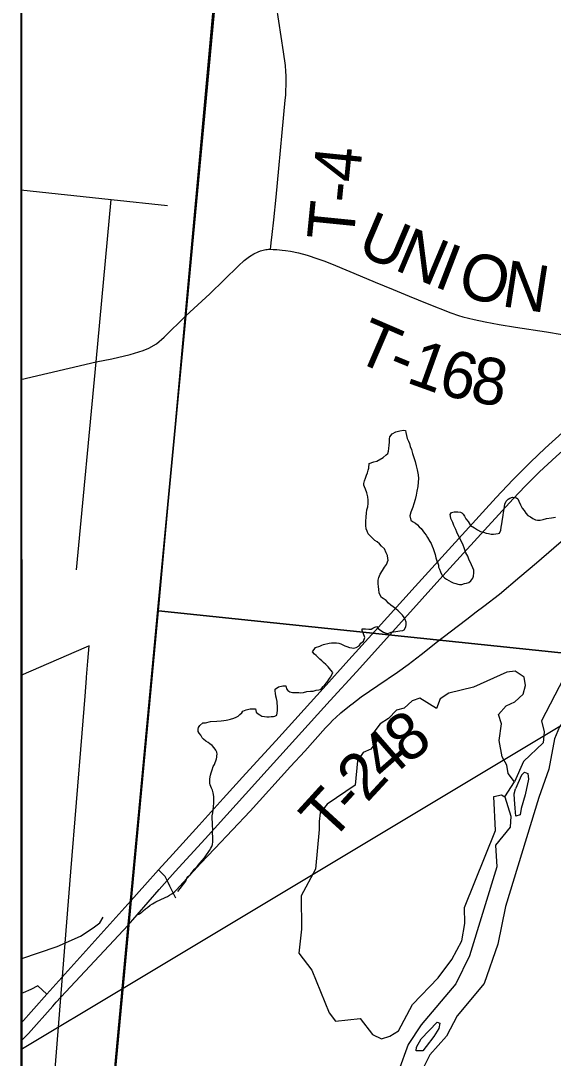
# Model space of a CAD drawing. Extents: x -1.4 to 35.4, y 0 to 22.
# Drawn here: x 24.49 to 25.138, y 16.414 to 17.676 of the extents above; entities that cross this region are included whole.
import ezdxf

# ---------------------------------------------------------------- set-up
doc = ezdxf.new("R2010")
doc.units = 0
for name, color, linetype in [('GM_X_City_Street', 7, 'Continuous'), ('GM_X_County_Text', 7, 'Continuous'), ('GM_X_Interchange_Ramps', 7, 'Continuous'), ('GM_X_Major_River', 7, 'Continuous'), ('GM_X_Minor_Lake', 7, 'Continuous'), ('GM_X_Minor_River', 7, 'Continuous'), ('GM_X_Rail_Line', 7, 'Continuous'), ('GM_X_Section', 7, 'Continuous'), ('GM_X_State_Route', 7, 'Continuous'), ('GM_X_Township_Road', 7, 'Continuous'), ('GM_X_Township_Road_Text', 7, 'Continuous'), ('SC_Scratch1', 7, 'Continuous'), ('SH_Border', 7, 'Continuous'), ('SH_Cut_Line', 7, 'Continuous')]:
    doc.layers.add(name, color=color, linetype=linetype)

msp = doc.modelspace()

# ---------------------------------------------------------------- linework, layer by layer
at = {"layer": 'GM_X_City_Street'}
for points in [[(24.4897, 17.47), (24.5998, 17.4582), (24.6682, 17.451)], [(24.5575, 17.008), (24.5813, 17.2609), (24.5998, 17.4582)], [(24.4897, 17.2395), (24.5813, 17.2609), (24.6004, 17.2644), (24.6228, 17.2697), (24.6386, 17.2746), (24.6457, 17.2776), (24.6551, 17.2829), (24.6642, 17.2908), (24.6908, 17.3168)], [(24.4897, 16.5348), (24.534, 16.5499), (24.5624, 16.5623), (24.578, 16.5727), (24.5858, 16.5787), (24.5899, 16.5854)]]:
    msp.add_lwpolyline(points, dxfattribs=at)
at = {"layer": 'GM_X_County_Text'}
msp.add_lwpolyline([(24.4897, 16.8794), (24.4897, 15.8886), (24.4962, 15.9571), (24.5508, 16.6406), (24.5643, 16.8095), (24.5679, 16.8544), (24.5697, 16.8763), (24.5697, 16.8774), (24.5713, 16.8967), (24.5728, 16.9155), (24.5693, 16.9139)], close=True, dxfattribs=at)
at = {"layer": 'GM_X_Interchange_Ramps'}
msp.add_lwpolyline([(24.5216, 16.4921), (24.5104, 16.5021), (24.5019, 16.4976), (24.4925, 16.4935), (24.4897, 16.4927)], dxfattribs=at)
at = {"layer": 'GM_X_Major_River'}
for points in [[(25.2185, 16.9085), (25.1999, 16.8899), (25.1453, 16.817), (25.1393, 16.8023), (25.1326, 16.7657), (25.1204, 16.7311), (25.0798, 16.5986), (25.0703, 16.5526), (25.0539, 16.5048), (25.021, 16.4655), (25.0079, 16.4408), (24.9876, 16.4182), (24.9772, 16.3972)], [(25.1502, 16.8757), (25.1235, 16.8244), (25.1266, 16.811), (25.1255, 16.7974), (25.1018, 16.7749), (25.0908, 16.7502)], [(25.0993, 16.7584), (25.1028, 16.7617), (25.1069, 16.7601), (25.1079, 16.7533), (25.1037, 16.7343), (25.0989, 16.7177), (25.0976, 16.7101), (25.0922, 16.7084), (25.0917, 16.7183), (25.0907, 16.7285), (25.0901, 16.7354), (25.0921, 16.7418)], [(25.0993, 16.7584), (25.0921, 16.7418)], [(25.079, 16.7319), (25.0908, 16.7502)], [(25.079, 16.7319), (25.0864, 16.7085), (25.0853, 16.6949), (25.0677, 16.6733), (25.0693, 16.6467), (25.0358, 16.5387), (25.0194, 16.5046), (24.9771, 16.4545), (24.9613, 16.4307), (24.9495, 16.3983)], [(24.9965, 16.458), (24.9999, 16.4568), (24.9986, 16.45), (24.9924, 16.4406), (24.983, 16.4283), (24.9791, 16.423), (24.9708, 16.4232), (24.9716, 16.4274), (24.9771, 16.4375)], [(24.9965, 16.458), (24.9771, 16.4375)]]:
    msp.add_lwpolyline(points, dxfattribs=at)
at = {"layer": 'GM_X_Minor_Lake'}
for points in [[(25.0908, 16.7502), (25.083, 16.7602), (25.0813, 16.7705), (25.0755, 16.7805), (25.0721, 16.8003), (25.0748, 16.8208), (25.0712, 16.8319), (25.0805, 16.8424), (25.0912, 16.8475), (25.1013, 16.8568), (25.1041, 16.8673), (25.1025, 16.8776), (25.0916, 16.8847), (25.0813, 16.8834), (25.0408, 16.8652), (25.0106, 16.8578), (25.0003, 16.8512), (24.9958, 16.8395), (24.9756, 16.8517), (24.9661, 16.8485), (24.9564, 16.8396), (24.9469, 16.8371), (24.9372, 16.827), (24.9272, 16.8208), (24.9194, 16.8107), (24.9233, 16.7996), (24.9159, 16.7898), (24.9064, 16.7858), (24.8997, 16.7757), (24.8969, 16.7461), (24.8626, 16.7229), (24.8541, 16.7124), (24.8531, 16.7018), (24.8529, 16.6923), (24.8485, 16.6441), (24.8312, 16.6114), (24.8315, 16.5711), (24.8282, 16.5416), (24.8441, 16.5211), (24.8651, 16.4694), (24.8729, 16.459), (24.9029, 16.4622), (24.9177, 16.4429), (24.929, 16.4377), (24.9389, 16.4409), (24.9493, 16.4472), (24.9666, 16.4795), (24.9976, 16.5116), (25.0144, 16.534), (25.0266, 16.5566), (25.0304, 16.5778), (25.0297, 16.5972), (25.0676, 16.691), (25.0654, 16.7325), (25.0749, 16.7345), (25.079, 16.7319), (25.079, 16.7319)], [(25.079, 16.7319), (25.0908, 16.7502)]]:
    msp.add_lwpolyline(points, dxfattribs=at)
at = {"layer": 'GM_X_Minor_River'}
for points in [[(24.9247, 16.9909), (24.9247, 16.9931), (24.9248, 16.9954), (24.9256, 16.9988), (24.9272, 17.0026), (24.9299, 17.0071), (24.9326, 17.0113), (24.935, 17.0143), (24.9369, 17.0196), (24.9366, 17.0218), (24.9359, 17.0253), (24.9344, 17.0287), (24.9326, 17.0333), (24.9289, 17.0368), (24.9262, 17.0395), (24.9236, 17.0418), (24.9206, 17.0438), (24.918, 17.0465), (24.915, 17.0492), (24.9124, 17.0519), (24.9113, 17.055), (24.9102, 17.058), (24.9099, 17.0618), (24.9096, 17.0668), (24.9101, 17.0725), (24.9105, 17.077), (24.911, 17.0808), (24.9122, 17.0846), (24.9126, 17.0888), (24.9127, 17.0926), (24.912, 17.0968), (24.9109, 17.1014), (24.9095, 17.106), (24.908, 17.109), (24.9073, 17.1109), (24.9073, 17.1128), (24.9081, 17.1162), (24.9093, 17.1196), (24.9105, 17.123), (24.9117, 17.1261), (24.9125, 17.1291), (24.9133, 17.1317), (24.9133, 17.1336), (24.9137, 17.1355), (24.9138, 17.1374), (24.9195, 17.1393), (24.9233, 17.14), (24.931, 17.1444), (24.9344, 17.1478), (24.9364, 17.1496), (24.9372, 17.1523), (24.9376, 17.1557), (24.938, 17.1595), (24.9385, 17.1633), (24.9385, 17.1671), (24.939, 17.1697), (24.9417, 17.1735), (24.9463, 17.1757), (24.9512, 17.1771), (24.9554, 17.1778), (24.9581, 17.1774), (24.9584, 17.1751), (24.9591, 17.1713), (24.9602, 17.1675), (24.9617, 17.1644), (24.9627, 17.1614), (24.9638, 17.1579), (24.9653, 17.1541), (24.9667, 17.1495), (24.9682, 17.1445), (24.9696, 17.1396), (24.971, 17.1346), (24.9721, 17.1296), (24.9735, 17.1235), (24.9738, 17.119), (24.9734, 17.1144), (24.9729, 17.1091), (24.9717, 17.1038), (24.9709, 17.0989), (24.9696, 17.0936), (24.968, 17.0883), (24.9668, 17.0841), (24.9652, 17.0803), (24.9644, 17.0781), (24.9632, 17.0735), (24.9647, 17.0682), (24.9665, 17.0666), (24.9703, 17.0647), (24.9726, 17.0627), (24.9748, 17.0604), (24.977, 17.0581), (24.9811, 17.0527), (24.983, 17.05), (24.9848, 17.0473), (24.9878, 17.0423), (24.9893, 17.04), (24.9904, 17.0369), (24.9918, 17.0339), (24.9929, 17.0304), (24.994, 17.0266), (24.9951, 17.0224)], [(24.9951, 17.0224), (24.9962, 17.019), (24.9972, 17.0159), (24.998, 17.0136), (24.9983, 17.0113), (24.9994, 17.0087), (25.0005, 17.0056), (25.0023, 17.0018), (25.0053, 16.9983), (25.0079, 16.9964), (25.0106, 16.9948), (25.0136, 16.9932), (25.0162, 16.992), (25.0192, 16.9912), (25.0219, 16.9904), (25.0238, 16.99), (25.0264, 16.9903), (25.0299, 16.9914), (25.0322, 16.9918), (25.0352, 16.9925), (25.0375, 16.9944), (25.0398, 16.9977), (25.0407, 17.0004), (25.0411, 17.0042), (25.0411, 17.0076), (25.0371, 17.0168), (25.0356, 17.0199), (25.0338, 17.0245), (25.0316, 17.0287), (25.0298, 17.0336), (25.0276, 17.039), (25.0254, 17.0436), (25.0236, 17.0471), (25.0221, 17.0501), (25.0206, 17.0539), (25.0192, 17.057), (25.0181, 17.0593), (25.017, 17.062), (25.0155, 17.0654), (25.0144, 17.0681), (25.0133, 17.0704), (25.0126, 17.0731), (25.0122, 17.0754), (25.0138, 17.0776), (25.0172, 17.0783), (25.0218, 17.0786), (25.0248, 17.0782), (25.0267, 17.0774), (25.0282, 17.0755), (25.0297, 17.0732), (25.0315, 17.0701), (25.0341, 17.0667), (25.0371, 17.062), (25.042, 17.0589), (25.0457, 17.0566), (25.0491, 17.0546), (25.0529, 17.0538), (25.0563, 17.0526), (25.0589, 17.0522), (25.0623, 17.0514), (25.065, 17.0513), (25.068, 17.0517), (25.0707, 17.052), (25.0726, 17.0527), (25.0742, 17.0561), (25.0746, 17.0599), (25.0751, 17.0637), (25.0755, 17.0667), (25.0768, 17.0743), (25.0772, 17.0777), (25.078, 17.0823), (25.0789, 17.088), (25.0804, 17.0914), (25.0828, 17.094), (25.0851, 17.0951), (25.0881, 17.0962), (25.0912, 17.0961), (25.093, 17.0957), (25.0949, 17.0942), (25.096, 17.0915), (25.0978, 17.0869), (25.1001, 17.0831), (25.1023, 17.08), (25.1045, 17.0769), (25.1071, 17.0742), (25.1101, 17.0723), (25.1128, 17.0703), (25.1161, 17.0687), (25.1188, 17.0683), (25.1218, 17.0683), (25.1256, 17.069), (25.1298, 17.0704), (25.1359, 17.0711), (25.1405, 17.0721)], [(24.801, 16.8514), (24.8003, 16.8545), (24.7996, 16.8579), (24.7992, 16.8606), (24.7993, 16.8628), (24.8035, 16.8658), (24.8088, 16.8669), (24.8123, 16.8668), (24.813, 16.8634), (24.8148, 16.8611), (24.8171, 16.8595), (24.8205, 16.8587), (24.8243, 16.8586), (24.8281, 16.8586), (24.8307, 16.8585), (24.8338, 16.8589), (24.838, 16.8599), (24.8425, 16.8602), (24.8456, 16.8606), (24.8494, 16.8617), (24.8524, 16.862), (24.8543, 16.8623), (24.8563, 16.8642), (24.8578, 16.8661), (24.8597, 16.868), (24.862, 16.8706), (24.8636, 16.8725), (24.8648, 16.8747), (24.8667, 16.8773), (24.8683, 16.8804), (24.8695, 16.883), (24.8672, 16.8861), (24.8639, 16.8899), (24.8609, 16.893), (24.8583, 16.8954), (24.856, 16.8973), (24.8538, 16.8992), (24.8519, 16.9012), (24.8493, 16.9039), (24.8474, 16.9054), (24.8448, 16.9081), (24.8483, 16.9134), (24.8537, 16.9152), (24.8563, 16.9163), (24.8582, 16.917), (24.8651, 16.9188), (24.8681, 16.9191), (24.8716, 16.9191), (24.8742, 16.919), (24.8769, 16.9186), (24.8795, 16.9178), (24.8818, 16.9166), (24.884, 16.9155), (24.8867, 16.9147), (24.8897, 16.9135), (24.8927, 16.913), (24.895, 16.9126), (24.898, 16.9133), (24.9015, 16.9156), (24.9038, 16.9186), (24.9069, 16.9212), (24.9085, 16.9257), (24.9067, 16.9303), (24.9052, 16.9341), (24.9052, 16.9364), (24.9094, 16.9364), (24.9132, 16.9359), (24.9162, 16.9359), (24.9182, 16.937), (24.9208, 16.9384), (24.9231, 16.9392), (24.9246, 16.9365), (24.928, 16.9341), (24.9314, 16.9322), (24.9344, 16.931), (24.9367, 16.9306), (24.9405, 16.932), (24.9462, 16.9331), (24.9511, 16.9338), (24.9546, 16.9341), (24.9565, 16.9348), (24.9584, 16.9386), (24.9588, 16.9413), (24.9589, 16.9443), (24.9578, 16.9474), (24.9563, 16.95), (24.9545, 16.9527), (24.9519, 16.9554), (24.9492, 16.9581), (24.9462, 16.9605), (24.9432, 16.9628), (24.9402, 16.9648), (24.9372, 16.9675), (24.9346, 16.9705), (24.9309, 16.9729), (24.929, 16.9744), (24.9268, 16.9779), (24.9261, 16.9798), (24.9257, 16.984), (24.925, 16.9878), (24.9247, 16.9909)], [(24.6807, 16.6169), (24.6908, 16.6293), (24.692, 16.633), (24.6935, 16.6349), (24.6958, 16.6372), (24.697, 16.6394), (24.6993, 16.6417), (24.7016, 16.6443), (24.7043, 16.6473), (24.7078, 16.6514), (24.7105, 16.6544), (24.7132, 16.6578), (24.7156, 16.6612), (24.7179, 16.6642), (24.7195, 16.6668), (24.721, 16.6694), (24.7222, 16.6717), (24.723, 16.674), (24.7234, 16.677), (24.7235, 16.6831), (24.7232, 16.6877), (24.7233, 16.6922), (24.723, 16.6972), (24.7228, 16.7086), (24.7236, 16.7124), (24.7241, 16.7162), (24.7245, 16.72), (24.7249, 16.7241), (24.7246, 16.7279), (24.7247, 16.7321), (24.7243, 16.7348), (24.724, 16.7367), (24.7229, 16.7401), (24.7218, 16.7424), (24.7211, 16.7443), (24.7204, 16.7463), (24.72, 16.7485), (24.7197, 16.7508), (24.7197, 16.7535), (24.7201, 16.7561), (24.7206, 16.7584), (24.7214, 16.7611), (24.7226, 16.7648), (24.7241, 16.7686), (24.7257, 16.7713), (24.7265, 16.7735), (24.7273, 16.7758), (24.7281, 16.7781), (24.7285, 16.78), (24.7285, 16.7819), (24.7289, 16.7838), (24.7282, 16.7864), (24.7271, 16.7887), (24.7253, 16.7914), (24.7226, 16.7945), (24.72, 16.7964), (24.7178, 16.798), (24.7151, 16.7996), (24.7121, 16.8019), (24.7106, 16.8038), (24.7088, 16.8069), (24.7069, 16.8092), (24.7058, 16.8115), (24.7055, 16.8142), (24.7059, 16.8161), (24.7075, 16.8187), (24.7113, 16.8217), (24.7144, 16.822), (24.7208, 16.8234), (24.7284, 16.8241), (24.7338, 16.8244), (24.7368, 16.8247), (24.7398, 16.825), (24.7417, 16.8254), (24.7452, 16.8265), (24.749, 16.8275), (24.752, 16.8286), (24.7543, 16.8301), (24.7563, 16.832), (24.7586, 16.8342), (24.7601, 16.8361), (24.764, 16.8379), (24.7689, 16.839), (24.7735, 16.8389), (24.7754, 16.8389), (24.7764, 16.8347), (24.7787, 16.8328), (24.7809, 16.8316), (24.7832, 16.83), (24.7862, 16.8296), (24.7893, 16.8292), (24.7919, 16.8291), (24.7946, 16.8295), (24.7972, 16.8294), (24.7991, 16.8298), (24.8014, 16.8313), (24.8019, 16.8339), (24.8023, 16.8369), (24.8023, 16.84), (24.8017, 16.848), (24.801, 16.8514)]]:
    msp.add_lwpolyline(points, dxfattribs=at)
at = {"layer": 'GM_X_Rail_Line'}
msp.add_line((24.4897, 16.4245), (24.6143, 16.4992), dxfattribs=at)
msp.add_lwpolyline([(24.6143, 16.4992), (25.2817, 16.8992), (25.9478, 17.2942), (26.588, 17.8861), (27.9508, 19.2702), (28.3499, 19.6392)], dxfattribs=at)
at = {"layer": 'GM_X_Section'}
for points in [[(25.7575, 17.8601), (25.6685, 16.8528), (24.6573, 16.9582), (24.7488, 17.9613)], [(25.6685, 16.8528), (25.5769, 15.8524), (24.5744, 15.9398), (24.5624, 15.9411), (24.6573, 16.9582)]]:
    msp.add_lwpolyline(points, close=True, dxfattribs=at)
at = {"layer": 'GM_X_State_Route'}
for p, q in [((24.5216, 16.4921), (24.6235, 16.6053)), ((24.4897, 16.4562), (24.5216, 16.4921))]:
    msp.add_line(p, q, dxfattribs=at)
for points in [[(24.6206, 16.576), (24.6314, 16.5884), (24.6583, 16.6194), (24.6679, 16.6301), (24.6778, 16.6412), (24.7143, 16.681), (24.7518, 16.7225), (24.7897, 16.7644), (24.8664, 16.8491), (24.8982, 16.884), (24.9316, 16.9208), (25.0036, 17.0006), (25.0543, 17.0561), (25.0891, 17.0942), (25.1037, 17.1095), (25.1213, 17.1271), (25.1412, 17.1458), (25.1607, 17.1633), (25.182, 17.1814), (25.1946, 17.1915)], [(24.6235, 16.6053), (24.6406, 16.6245), (24.6574, 16.6431), (24.6747, 16.6623), (24.707, 16.6976), (24.7362, 16.7299), (24.7636, 16.7603), (24.8002, 16.8001), (24.8576, 16.8638), (24.8889, 16.8983), (24.9211, 16.9337), (24.9696, 16.9878), (25.0102, 17.0323), (25.0685, 17.096), (25.0886, 17.1172), (25.1101, 17.1387), (25.128, 17.1558), (25.1492, 17.175)], [(24.5287, 16.4774), (24.5328, 16.4821), (24.6206, 16.576)], [(24.4897, 16.4349), (24.499, 16.4439), (24.5287, 16.4774)]]:
    msp.add_lwpolyline(points, dxfattribs=at)
at = {"layer": 'GM_X_Township_Road'}
msp.add_line((24.6785, 16.6086), (24.6754, 16.615), dxfattribs=at)
for points in [[(24.7936, 17.3978), (24.794, 17.4013), (24.7945, 17.4058), (24.7959, 17.4159), (24.7979, 17.4335), (24.8004, 17.4611), (24.8038, 17.4959), (24.808, 17.5398), (24.8117, 17.5793), (24.8122, 17.5852), (24.8125, 17.5907), (24.8129, 17.5975), (24.8129, 17.6031), (24.8128, 17.6087), (24.8124, 17.6139), (24.8119, 17.6212), (24.8097, 17.6378), (24.8008, 17.6937)], [(24.6908, 17.3168), (24.7198, 17.3436), (24.7548, 17.3776), (24.7617, 17.3841), (24.7682, 17.3889), (24.7736, 17.3921), (24.7788, 17.3946), (24.7817, 17.3957), (24.7848, 17.3966), (24.7879, 17.3974), (24.7896, 17.3976), (24.7914, 17.3978), (24.7936, 17.3978)], [(24.7936, 17.3978), (24.797, 17.3976), (24.8012, 17.3974), (24.808, 17.3968), (24.812, 17.3963), (24.818, 17.3954), (24.8278, 17.3934), (24.8385, 17.3905), (24.8515, 17.3863), (24.8597, 17.3833), (24.8728, 17.3779), (24.9027, 17.3655), (24.921, 17.3579), (24.9428, 17.3489), (24.9623, 17.3408), (24.9842, 17.332), (25.0131, 17.3206), (25.0224, 17.3174), (25.028, 17.3158), (25.0345, 17.314), (25.0416, 17.3124), (25.0548, 17.3094), (25.0719, 17.3061), (25.0918, 17.3029), (25.1295, 17.2972), (25.1486, 17.2943)], [(24.892, 16.8441), (24.8928, 16.8447), (24.9042, 16.8534), (24.9244, 16.8672), (24.9483, 16.8834), (24.9612, 16.893), (24.9771, 16.905), (24.9971, 16.9207), (25.0123, 16.9326), (25.0325, 16.948), (25.0442, 16.9569), (25.0533, 16.9636), (25.0724, 16.9783), (25.0973, 16.9993), (25.1176, 17.0166), (25.1536, 17.0477)], [(24.6754, 16.615), (24.6771, 16.6167), (24.6792, 16.6188), (24.7086, 16.6509), (24.7258, 16.6689), (24.7688, 16.7145), (24.8182, 16.7687), (24.8353, 16.7876), (24.8607, 16.8157), (24.8654, 16.8207), (24.8697, 16.8251), (24.8732, 16.8283), (24.8792, 16.8339), (24.892, 16.8441)], [(24.6679, 16.6301), (24.6661, 16.6334), (24.6653, 16.6349), (24.6641, 16.6364), (24.6623, 16.6383), (24.6591, 16.6414), (24.6574, 16.6431)], [(24.6754, 16.615), (24.6728, 16.6202), (24.6711, 16.6234), (24.669, 16.6279), (24.6679, 16.6301)], [(24.6314, 16.5884), (24.6344, 16.5898), (24.6359, 16.5908), (24.6371, 16.5917), (24.6389, 16.5931), (24.6416, 16.5956), (24.644, 16.5975), (24.6474, 16.6), (24.6501, 16.6019), (24.6519, 16.603), (24.654, 16.6042), (24.6654, 16.6094), (24.6682, 16.6108), (24.6706, 16.6122), (24.6734, 16.6138), (24.6754, 16.615)]]:
    msp.add_lwpolyline(points, dxfattribs=at)
at = {"layer": 'SC_Scratch1'}
for points in [[(26.9481, 19.8546), (24.4897, 19.8546), (24.4897, 14.8759)], [(24.8423, 18.9651), (24.7507, 17.961), (24.7137, 17.5642), (24.6906, 17.3173), (24.6565, 16.9596), (24.6233, 16.6059), (24.6203, 16.5765), (24.5837, 16.1806)], [(24.5837, 16.1806), (24.6203, 16.5765), (24.6233, 16.6059), (24.6565, 16.9596), (24.6906, 17.3173), (24.7137, 17.5642), (24.7507, 17.961), (24.8423, 18.9651)]]:
    msp.add_lwpolyline(points, dxfattribs=at)
at = {"layer": 'SH_Border'}
msp.add_lwpolyline([(24.4897, 19.8546), (24.4921, 13.0546), (31.2897, 13.0546), (31.2897, 19.8546)], close=True, dxfattribs=at)
at = {"layer": 'SH_Cut_Line'}
for points in [[(26.9481, 19.8546), (24.4897, 19.8546), (24.4897, 14.8759)], [(24.5837, 16.1806), (24.6203, 16.5765), (24.6233, 16.6059), (24.6565, 16.9596), (24.6906, 17.3173), (24.7137, 17.5642), (24.7507, 17.961), (24.8423, 18.9651)], [(24.8423, 18.9651), (24.7507, 17.961), (24.7137, 17.5642), (24.6906, 17.3173), (24.6565, 16.9596), (24.6233, 16.6059), (24.6203, 16.5765), (24.5837, 16.1806)]]:
    msp.add_lwpolyline(points, dxfattribs=at)

# ---------------------------------------------------------------- texts
at = {"layer": 'GM_X_Township_Road_Text'}
for s, height, rotation, p in [('T-4', 0.05682, 84.3024, (24.8945, 17.4065)), ('U', 0.0568, 336.9234, (24.8967, 17.3931)), ('N', 0.0568, 337.1687, (24.9429, 17.3734)), ('I', 0.0568, 338.9107, (24.9908, 17.3533)), ('O', 0.0568, 345.2529, (25.0191, 17.3428)), ('N', 0.0568, 351.1462, (25.0737, 17.3288)), ('T', 0.0568, 336.6824, (24.8933, 17.2634)), ('1', 0.0568, 340.1679, (24.9574, 17.2364)), ('6', 0.0568, 345.5487, (24.9959, 17.2228)), ('-', 0.0568, 337.6711, (24.9333, 17.2462)), ('8', 0.0568, 350.6924, (25.0352, 17.2129)), ('8', 0.0568, 35.2736, (24.9589, 16.7705)), ('4', 0.0568, 41.0726, (24.9337, 16.7484)), ('2', 0.0568, 47.236, (24.9111, 16.7238)), ('T', 0.0568, 47.5904, (24.8668, 16.6753)), ('-', 0.0568, 47.537, (24.8954, 16.7067))]:
    msp.add_text(s, height=height, rotation=rotation, dxfattribs=at).set_placement(p)

doc.saveas('drawing.dxf')
